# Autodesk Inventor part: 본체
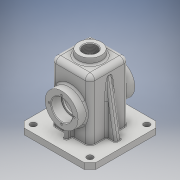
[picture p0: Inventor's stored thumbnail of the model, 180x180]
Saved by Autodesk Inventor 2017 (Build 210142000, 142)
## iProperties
Part Number: 본체
Material: 일반
Document SubType Name: Modeling
Designer: 20
Density: 1 g/cm^3
Appearance: 기본값
Mass: 292.115 g
Surface Area: 897.365 cm^2
Volume: 292.115 cm^3
Author: 20
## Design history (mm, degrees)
sketch "스케치1"
  geometry: L1 (-32.5, -50)-(32.5, -50); L2 (32.5, -50)-(32.5, 50); L3 (32.5, 50)-(-32.5, 50); L4 (-32.5, 50)-(-32.5, -50); L5 (-32.5, -50)-(32.5, 50); L6 (32.5, -50)-(-32.5, 50); 1 further point
  constraints: 12 end point, 2 midpoint, 2 parallel, 1 horizontal, 1 perpendicular
  dimensions: "d0" = 65 distance of L3.end L2.end; "d1" = 100 distance of L2.end L1.end
extrude "돌출1" new body sketch "스케치1" stored distance "d2" = 65; taper "d3" = 0 deg
sketch "스케치2"
  geometry: L1 (60, -5)-(5, -5); L2 (5, -5)-(5, -60); L3 (5, -60)-(60, -60); L4 (60, -60)-(60, -5); L5 (60, -5)-(5, -60); L6 (5, -5)-(60, -60); 1 further point
  constraints: 12 end point, 2 midpoint, 2 parallel, 1 horizontal, 1 perpendicular
  dimensions: "d4" = 55 distance of L3.end L2.end; "d5" = 55 distance of L2.end L1.end
extrude "돌출2" cut sketch "스케치2" distance "d6" = 95; taper "d7" = 0 deg
sketch "스케치3"
  geometry: L1 (92.5, 27.5)-(-27.5, 27.5); L2 (-27.5, 27.5)-(-27.5, -92.5); L3 (-27.5, -92.5)-(92.5, -92.5); L4 (92.5, -92.5)-(92.5, 27.5); L5 (92.5, 27.5)-(-27.5, -92.5); L6 (-27.5, 27.5)-(92.5, -92.5); L7 (5, -60)-(5, -5) reference; L8 (60, -60)-(5, -60) reference; L9 (60, -5)-(60, -60) reference; L10 (5, -5)-(60, -5) reference; 1 further point
  constraints: 12 end point, 2 midpoint, 2 parallel, 1 horizontal, 1 perpendicular
  dimensions: "d8" = 120 distance of L3.end L2.end; "d9" = 120 distance of L2.end L1.end
extrude "돌출3" join sketch "스케치3" distance "d10" = 10; taper "d11" = 0 deg
sketch "스케치5"
  geometry: L1 (60, -60)-(-60, -60) reference; C1 r 27.5 at (0, -5); 1 further point
  constraints: 1 centre point, 1 vertical alignment
  dimensions: "d12" = 55 diameter of C1; "d13" = 55 distance from line of L1 C1.centre
extrude "돌출4" join sketch "스케치5" distance "d14" = 15; taper "d15" = 0 deg
hole "구멍1" diameter "d19" = 30; stored, may be unused: countersink angle "d23" = 90 deg, drill point angle "d25" = 0 deg; dims "d17" = 10, "d18" = 10, "d20" = 6, "d21" = 35, "d22" = 17, "d24" = 30
sketch "스케치7"
  geometry: C1 r 17.5 at (0, 0) reference; 2 further points
  constraints: 1 vertical alignment
  dimensions: "d26" = 21 distance of C1.centre point (0, 21)
hole "구멍2" sketch "스케치7" at (0, 21) diameter "d27" = 3.242; stored, may be unused: countersink angle "d31" = 90 deg, drill point angle "d33" = 118 deg; dims "d28" = 8, "d29" = 19.05, "d30" = 4.775, "d32" = 10
sketch "스케치8"
  geometry: C1 r 20 at (32.5, -32.5); 1 further point
  constraints: 1 centre point, 1 coincident
  dimensions: "d37" = 40 diameter of C1
extrude "돌출5" join sketch "스케치8" distance "d38" = 10; taper "d39" = 0 deg
feature "면 기울기1" dims angle "d40" = 5 deg
hole "구멍3" diameter "d43" = 22.835; stored, may be unused: countersink angle "d47" = 90 deg, drill point angle "d49" = 0 deg; dims "d41" = 10, "d42" = 10, "d44" = 50, "d45" = 4, "d46" = 2, "d48" = 30
fillet "모깎기1" dims "d50" = 8
fillet "모깎기2" dims "d51" = 3
fillet "모깎기3" dims "d52" = 3
chamfer "모따기1" distance "d54" = 1; stored, may be unused: second distance "d55" = 2, angle "d56" = 45 deg
sketch "스케치9"
  geometry: L1 (48, -50)-(42.522, -18.936); L2 (60, -50)-(60, -60) reference; L3 (60, -50)-(-60, -50) reference; 1 further point
  constraints: 2 end point, 1 point on line
  dimensions: "d57" = 10 deg angle of L2 L1; "d58" = 12 distance of L2.start L1.start; "d59" = 31.06445 vertical distance of L1.start L1.end
feature "리브1" sketch "스케치9" dims "d60" = 1, "d61" = 10, "d62" = 0, "d63" = 0, "d64" = 1, "d65" = 1
fillet "모깎기5" dims "d66" = 3
fillet "모깎기6" dims "d67" = 3
sketch "스케치11"
  geometry: L1 (-57, -65)-(-8, -65) reference; L2 (-57, -60)-(-8, -60) reference; L3 (-35.5, -60)-(-29.5, -60); L4 (-29.5, -60)-(-29.5, -75); L5 (-29.5, -75)-(-35.5, -75); L6 (-35.5, -75)-(-35.5, -60); 2 further points
  constraints: 8 end point, 2 midpoint, 2 parallel, 1 horizontal, 1 perpendicular
  dimensions: "d69" = 6 distance of L4.end L5.end; "d70" = 15 distance of L5.end L3.start
extrude "돌출6" join sketch "스케치11" distance "d71" = 20; taper "d72" = 0 deg
fillet "모깎기7" dims "d73" = 3
fillet "모깎기8" dims "d74" = 3
fillet "모깎기13" dims "d79" = 3
fillet "모깎기14" dims "d80" = 3
chamfer "모따기2" distance "d82" = 10; stored, may be unused: second distance "d83" = 2, angle "d84" = 45 deg
sketch "스케치12"
  geometry: C1 r 5 at (-15, -80); 1 further point
  constraints: 1 centre point
  dimensions: "d86" = 10 diameter of C1; "d87" = 47.5 horizontal distance of C1.centre point (32.5, -32.5); "d88" = 47.5 horizontal distance of point (32.5, -32.5) C1.centre
extrude "돌출7" cut sketch "스케치12" distance "d89" = 15; taper "d90" = 0 deg
node "작업 평면2"
sketch "스케치13"
  geometry: L1 (-19.125, -60)-(19.125, -60) reference; L2 (32.5, -42)-(32.5, 50) reference; 2 further points
  constraints: 1 other
  dimensions: "d98" = 26 distance from line of point (0, -34) L1; "d99" = 32.5 distance from line of L2 point (0, -34)
feature "엠보싱1" sketch "스케치13" dims "d100" = 0.5, "d101" = 0
fillet "모깎기15" dims "d102" = 1
chamfer "모따기3" distance "d103" = 1; stored, may be unused: second distance "d104" = 2, angle "d105" = 45 deg
fillet "모깎기16" dims "d106" = 0.3
node "솔리드1"
mirror "미러1"
mirror "미러2"
pattern_circular "원형 패턴1" dims angle "d35" = 360 deg
mirror "미러3"
mirror "미러4"
mirror "미러5"
pattern_linear "직사각형 패턴1" dims "d93" = 95, "d96" = 95
node "작업 평면1"
other parameters: "d97" = 13
